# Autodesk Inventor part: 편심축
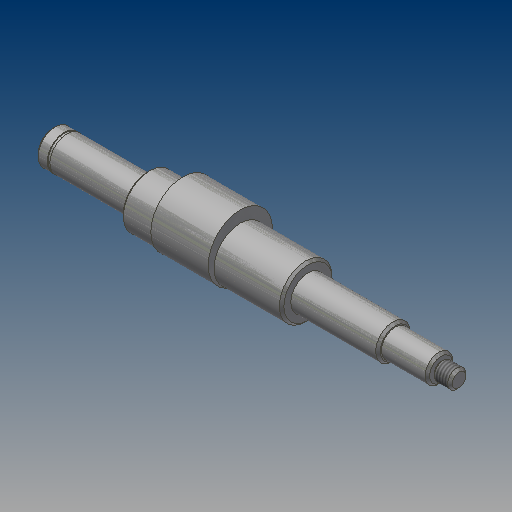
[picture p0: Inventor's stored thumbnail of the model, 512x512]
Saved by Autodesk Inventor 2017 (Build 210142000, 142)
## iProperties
Created: 2015-09
Part Number: 편심축
Material: 강철, 연강
Document SubType Name: Modeling
Designer: mduedu
Density: 1 g/cm^3
Appearance: 강철
Author: mduedu
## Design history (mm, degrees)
sketch "스케치1"
  geometry: L1 (-88.5, 0)-(88.5, 0); L2 (-88.5, 0)-(-88.5, 7.5); L3 (-88.5, 7.5)-(-47.35, 7.5); L4 (-47.35, 7.5)-(-47.35, 11.5); L5 (-47.35, 11.5)-(22.65, 11.5); L6 (22.65, 11.5)-(22.65, 7.5); L7 (22.65, 7.5)-(60.65, 7.5); L8 (60.65, 7.5)-(60.65, 6); L9 (60.65, 6)-(80.65, 6); L10 (80.65, 6)-(80.65, 3); L11 (80.65, 3)-(81.65, 3); L12 (81.65, 3)-(81.65, 4); L13 (81.65, 4)-(88.5, 4); L14 (88.5, 4)-(88.5, 0); 2 further points
  constraints: 28 end point, 10 parallel, 2 perpendicular, 1 coincident, 1 collinear, 1 horizontal, 1 midpoint
  dimensions: "d0" = 41.15 distance of L2.end L3.end; "d2" = 70 distance of L4.end L5.end; "d3" = 38 distance of L6.end L7.end; "d4" = 177 distance of L1.start L1.end; "d5" = 20 distance of L8.end L9.end; "d6" = 1 distance of L10.end L11.end; "d7" = 8 diameter of L13 L1; "d8" = 6 diameter of L11 L1; "d9" = 12 diameter of L9 L1; "d10" = 15 diameter of L7 L1; "d11" = 23 diameter of L5 L1; "d12" = 15 diameter of L3 L1
revolve "회전1" sketch "스케치1" stored, may be unused: angle "d13" = 90 deg
sketch "스케치2"
  geometry: L1 (-88.5, 7.5)-(-47.35, 7.5) reference; L2 (-88.5, -7.5)-(-88.5, 7.5) reference; L3 (88.5, -4)-(88.5, 4) reference; L4 (-88.5, 0)-(88.5, 0); L5 (-83.5, 7.5)-(-82.35, 7.5); L6 (-82.35, 7.5)-(-82.35, 7.15); L7 (-82.35, 7.15)-(-83.5, 7.15); L8 (-83.5, 7.15)-(-83.5, 7.5); 1 further point
  constraints: 10 end point, 2 midpoint, 2 parallel, 1 horizontal, 1 perpendicular, 1 point on line
  dimensions: "d14" = 5 distance between parallel lines of L8 L2; "d15" = 14.3 diameter of L7 L4; "d16" = 1.15 distance of L6.end L7.end
revolve "회전2" sketch "스케치2" stored, may be unused: angle "d17" = 90 deg
node "작업 평면1"
sketch "스케치3"
  geometry: C1 r 11.5 at (0, 0) reference; C2 r 14 at (0, 2.5); 1 further point
  constraints: 1 centre point, 1 tangent, 1 vertical alignment
  dimensions: "d19" = 28 diameter of C2
extrude "돌출1" join sketch "스케치3" distance "d21" = 25; taper "d22" = 0 deg
node "작업 평면2"
sketch "스케치4"
  geometry: L1 (10, 7.5)-(10, -7.5) reference; L2 (-10, 6)-(-10, -6) reference; L3 (10, 0)-(-10, 0); L4 (-5, -2)-(3, -2); L5 (3, 2)-(-5, 2); A1 r 2 centre (3, 0) between (3, -2) and (3, 2); A2 r 2 centre (-5, 0) between (-5, 2) and (-5, -2); 1 further point
  constraints: 6 end point, 4 point on circle, 4 tangent, 2 centre point, 2 midpoint, 2 parallel, 1 point on line
  dimensions: "d23" = 4 distance between parallel lines of L5 L4; "d25" = 12 dimension on A2 A1; "d26" = 3 distance edge to line of A2 L2
extrude "돌출2" cut sketch "스케치4" distance "d27" = 2.5; taper "d28" = 0 deg
chamfer "모따기1" distance "d29" = 1; stored, may be unused: second distance "d30" = 2, angle "d31" = 45 deg
feature "스레드1" dims "d32" = 10, "d33" = 0
chamfer "모따기2" distance "d34" = 1; stored, may be unused: second distance "d35" = 2, angle "d36" = 45 deg
chamfer "모따기3" distance "d37" = 1; stored, may be unused: second distance "d38" = 2, angle "d39" = 45 deg
node "솔리드1"
other parameters: "d18" = -29.5
